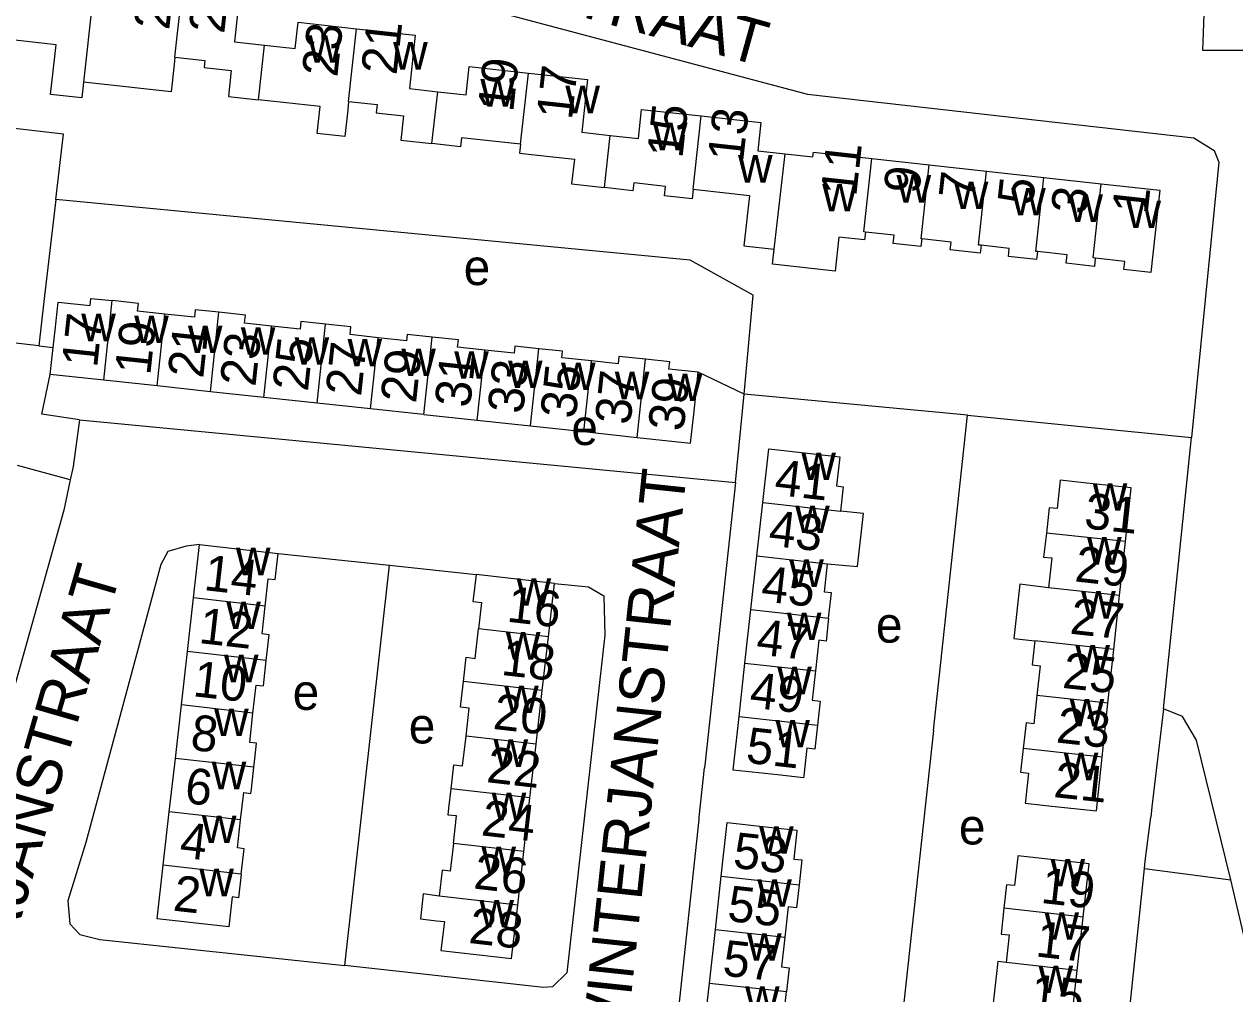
# Model space of a CAD drawing. Extents: x 161936 to 163647, y 386450 to 388633.
# Drawn here: x 162355.2 to 162490.7, y 387685.1 to 387793.6 of the extents above; entities that cross this region are included whole.
import ezdxf

# ---------------------------------------------------------------- set-up
doc = ezdxf.new("R2010")
doc.units = 0
for name, color, linetype in [('BLT_Basislijn', 7, 'Continuous'), ('BLT_Bebouwing', 7, 'Continuous'), ('BLT_Centroide', 7, 'Continuous'), ('BLT_Huisnummer', 7, 'Continuous'), ('BLT_Huisnummer_ tussenligend', 7, 'Continuous'), ('BLT_Onderverdeling_panden', 7, 'Continuous'), ('BLT_Straatnaam', 7, 'Continuous'), ('BLT_Vlakafsluiter', 7, 'Continuous')]:
    doc.layers.add(name, color=color, linetype=linetype)

msp = doc.modelspace()

# ---------------------------------------------------------------- linework, layer by layer
at = {"layer": 'BLT_Basislijn'}
for p, q in [((162356.86, 387757.65), (162358.48, 387757.44)), ((162434.82, 387742.35), (162435.82, 387752.22)), ((162460.8, 387749.87), (162435.82, 387752.22)), ((162457, 387714.58), (162460.8, 387749.87)), ((162460.8, 387749.87), (162485.87, 387747.39)), ((162361.43, 387749.36), (162434.82, 387742.35)), ((162482.75, 387717.02), (162485.87, 387747.39)), ((162360.39, 387742.63), (162354.47, 387744.25)), ((162383.65, 387734.4), (162396.12, 387733.09)), ((162391.1, 387688.31), (162396.12, 387733.09)), ((162396.12, 387733.09), (162405.8, 387732.07)), ((162457, 387714.58), (162448.91, 387640.49)), ((162427.81, 387677.24), (162430.77, 387704.64)), ((162474.31, 387639.43), (162480.61, 387699.15)), ((162480.61, 387699.15), (162490.26, 387697.9))]:
    msp.add_line(p, q, dxfattribs=at)
for points in [[(162502.48, 387814.29), (162501.34, 387810.13), (162499.33, 387800.3), (162497.01, 387793.33), (162495.42, 387791.61), (162493.28, 387790.67), (162487.12, 387790.69), (162487.41, 387797.79)], [(162303.81, 387812.76), (162305.9, 387812.89), (162310.22, 387812.55), (162362.08, 387807.27), (162442.89, 387785.78), (162486.12, 387780.93), (162488.41, 387779.48), (162488.92, 387778.18), (162485.87, 387747.39)], [(162436.82, 387763.29), (162429.77, 387767.21), (162358.77, 387774.02)], [(162435.82, 387752.22), (162436.82, 387763.29)], [(162361.43, 387749.36), (162357.2, 387750.01), (162358.16, 387754.43)], [(162361.43, 387749.36), (162360.71, 387744.14), (162360.39, 387742.63)], [(162360.39, 387742.63), (162359.67, 387739.24), (162347.85, 387697.16), (162347.68, 387696.55)], [(162434.82, 387742.35), (162431.44, 387711.06), (162431.38, 387710.43)], [(162374.87, 387735.4), (162373.38, 387735.23), (162371.32, 387734.62), (162370.52, 387733.19), (162362.13, 387702.07), (162360.11, 387695.53), (162360.35, 387692.95), (162361.45, 387691.77), (162363.71, 387691.23), (162391.1, 387688.31)], [(162414.59, 387731.06), (162418.38, 387730.66), (162420.12, 387729.68), (162420.23, 387725.26), (162415.98, 387687.47), (162414.37, 387685.93), (162413.34, 387685.85), (162391.1, 387688.31)], [(162482.75, 387717.02), (162481.44, 387706.07), (162481.3, 387704.89)], [(162490.26, 387697.9), (162486.44, 387713.53), (162484.85, 387716.16), (162482.75, 387717.02)], [(162430.77, 387704.64), (162430.79, 387704.9), (162431.38, 387710.43)], [(162480.61, 387699.15), (162480.69, 387699.98), (162481.3, 387704.89)], [(162481.44, 387634.62), (162492.55, 387679.45), (162492.68, 387685.02), (162492.39, 387688.84), (162490.26, 387697.9)]]:
    msp.add_lwpolyline(points, dxfattribs=at)
at = {"layer": 'BLT_Bebouwing'}
for p, q in [((162450.11, 387778.59), (162456.52, 387777.88)), ((162456.52, 387777.88), (162462.93, 387777.18)), ((162462.93, 387777.18), (162469.35, 387776.47)), ((162469.35, 387776.47), (162475.76, 387775.77)), ((162358.16, 387754.43), (162358.48, 387757.44)), ((162364.13, 387753.79), (162358.16, 387754.43)), ((162370.1, 387753.15), (162364.13, 387753.79)), ((162376.08, 387752.51), (162370.1, 387753.15)), ((162382.05, 387751.87), (162376.08, 387752.51)), ((162388.02, 387751.24), (162382.05, 387751.87)), ((162393.99, 387750.6), (162388.02, 387751.24)), ((162399.96, 387749.96), (162405.93, 387749.32)), ((162405.93, 387749.32), (162411.9, 387748.68)), ((162411.9, 387748.68), (162417.87, 387748.04)), ((162417.87, 387748.04), (162423.84, 387747.4)), ((162437.24, 387734.13), (162437.91, 387740.12)), ((162374.19, 387729.43), (162374.87, 387735.4)), ((162374.87, 387735.4), (162383.65, 387734.4)), ((162477.83, 387729.71), (162478.48, 387735.73)), ((162436.57, 387728.14), (162437.24, 387734.13)), ((162414.59, 387731.06), (162405.8, 387732.07)), ((162413.9, 387725.07), (162414.59, 387731.06)), ((162373.51, 387723.45), (162374.19, 387729.43)), ((162477.18, 387723.68), (162477.83, 387729.71)), ((162435.9, 387722.15), (162436.57, 387728.14)), ((162413.21, 387719.07), (162413.9, 387725.07)), ((162372.83, 387717.46), (162373.51, 387723.45)), ((162476.52, 387717.66), (162477.18, 387723.68)), ((162435.23, 387716.16), (162435.9, 387722.15)), ((162412.53, 387713.07), (162413.21, 387719.07)), ((162372.15, 387711.48), (162372.83, 387717.46)), ((162475.88, 387711.63), (162476.52, 387717.66)), ((162434.56, 387710.17), (162435.23, 387716.16)), ((162411.84, 387707.07), (162412.53, 387713.07)), ((162371.47, 387705.5), (162372.15, 387711.48)), ((162475.23, 387705.6), (162475.88, 387711.63)), ((162411.15, 387701.07), (162411.84, 387707.07)), ((162370.79, 387699.52), (162371.47, 387705.5)), ((162433.25, 387698.31), (162433.92, 387704.3)), ((162410.46, 387695.07), (162411.15, 387701.07)), ((162473.74, 387693.72), (162474.41, 387699.68)), ((162432.59, 387692.32), (162433.25, 387698.31)), ((162473.06, 387687.75), (162473.74, 387693.72)), ((162431.93, 387686.33), (162432.59, 387692.32)), ((162472.39, 387681.78), (162473.06, 387687.75)), ((162431.26, 387680.35), (162431.93, 387686.33))]:
    msp.add_line(p, q, dxfattribs=at)
for points in [[(162373.02, 387798.35), (162379.42, 387797.64), (162378.76, 387791.64), (162382.14, 387791.27)], [(162361.89, 387787.14), (162361.69, 387785.37), (162358.19, 387785.76), (162358.81, 387791.33), (162352.53, 387792.02), (162352.75, 387794.03)], [(162382.14, 387791.27), (162385.56, 387790.89), (162385.88, 387793.84), (162392.44, 387793.12)], [(162392.44, 387793.12), (162399, 387792.4), (162398.35, 387786.42), (162401.51, 387786.07)], [(162372.1, 387789.95), (162372.02, 387789.13), (162371.68, 387786.05), (162361.89, 387787.14)], [(162372.1, 387789.95), (162375.46, 387789.58), (162375.37, 387788.77), (162378.41, 387788.43), (162378.1, 387785.53), (162381.46, 387785.16)], [(162401.51, 387786.07), (162404.68, 387785.72), (162405.02, 387788.89), (162411.66, 387788.16)], [(162411.66, 387788.16), (162418.29, 387787.43), (162417.64, 387781.53), (162420.81, 387781.18)], [(162391.54, 387784.98), (162391.44, 387784.06), (162391.11, 387781.07), (162388.03, 387781.41), (162388.36, 387784.4), (162381.46, 387785.16)], [(162391.54, 387784.98), (162394.74, 387784.63), (162394.64, 387783.71), (162397.68, 387783.38), (162397.39, 387780.64), (162400.87, 387780.26)], [(162358.77, 387774.02), (162359.62, 387781.31), (162336, 387784.06)], [(162420.81, 387781.18), (162423.98, 387780.83), (162424.33, 387784.09), (162431.01, 387783.36)], [(162431.01, 387783.36), (162437.68, 387782.62), (162437.33, 387779.46), (162440.41, 387779.12)], [(162410.78, 387780.19), (162404.17, 387780.92), (162404.06, 387779.91), (162400.87, 387780.26)], [(162410.78, 387780.19), (162410.67, 387779.18), (162413.74, 387778.85), (162416.81, 387778.51), (162416.5, 387775.75), (162420.17, 387775.34)], [(162440.41, 387779.12), (162443.49, 387778.79), (162443.55, 387779.31), (162450.11, 387778.59)], [(162356.86, 387757.65), (162351.03, 387758.32), (162353.1, 387776.06), (162341.35, 387777.43), (162338.25, 387750.82)], [(162430.1, 387775.15), (162429.99, 387774.1), (162426.88, 387774.44), (162427, 387775.48), (162423.46, 387775.87), (162423.36, 387774.99), (162420.17, 387775.34)], [(162475.76, 387775.77), (162482.33, 387775.04), (162481.31, 387765.86), (162478.31, 387766.19), (162478.41, 387767.08), (162475.1, 387767.45)], [(162430.1, 387775.15), (162436.4, 387774.45), (162435.78, 387768.83), (162439.18, 387768.45)], [(162358.77, 387774.02), (162357.44, 387762.61), (162356.86, 387757.65)], [(162449.37, 387770.37), (162449.28, 387769.49), (162446.4, 387769.81), (162445.98, 387765.99), (162438.99, 387766.76)], [(162455.68, 387769.6), (162455.59, 387768.76), (162452.48, 387769.1), (162452.58, 387770.02), (162449.37, 387770.37)], [(162462.32, 387768.89), (162462.22, 387768), (162458.87, 387768.37), (162458.96, 387769.23), (162455.68, 387769.6)], [(162468.63, 387768.19), (162468.53, 387767.29), (162465.38, 387767.64), (162465.48, 387768.54), (162462.32, 387768.89)], [(162438.99, 387766.76), (162439.18, 387768.45)], [(162475.1, 387767.45), (162475, 387766.52), (162471.86, 387766.87), (162471.96, 387767.82), (162468.63, 387768.19)], [(162358.48, 387757.44), (162358.69, 387759.4), (162359.03, 387762.52), (162362.62, 387762.14), (162362.71, 387762.95), (162365.09, 387762.7)], [(162370.96, 387761.18), (162367.91, 387761.51), (162368.01, 387762.38), (162365.09, 387762.7)], [(162377.03, 387761.4), (162374.37, 387761.68), (162374.28, 387760.83), (162370.96, 387761.18)], [(162382.9, 387759.84), (162379.9, 387760.16), (162380, 387761.08), (162377.03, 387761.4)], [(162388.96, 387760.08), (162386.21, 387760.37), (162386.11, 387759.5), (162382.9, 387759.84)], [(162394.84, 387758.55), (162391.7, 387758.89), (162391.79, 387759.77), (162388.96, 387760.08)], [(162400.89, 387758.62), (162398.09, 387758.92), (162398.01, 387758.21), (162394.84, 387758.55)], [(162406.77, 387757.17), (162403.74, 387757.49), (162403.83, 387758.31), (162400.89, 387758.62)], [(162412.82, 387757.32), (162410.16, 387757.6), (162410.08, 387756.81), (162406.77, 387757.17)], [(162418.72, 387755.95), (162415.39, 387756.31), (162415.47, 387757.04), (162412.82, 387757.32)], [(162424.78, 387756.14), (162421.8, 387756.46), (162421.71, 387755.63), (162418.72, 387755.95)], [(162430.66, 387754.69), (162427.39, 387755.04), (162427.48, 387755.85), (162424.78, 387756.14)], [(162423.84, 387747.4), (162429.81, 387746.76), (162430.16, 387750), (162430.35, 387751.74), (162430.66, 387754.69)], [(162399.96, 387749.96), (162399.56, 387750), (162393.99, 387750.6)], [(162437.91, 387740.12), (162438.58, 387746.1)], [(162438.58, 387746.1), (162443.55, 387745.55), (162446.52, 387745.22), (162446.15, 387741.97), (162446.9, 387741.88), (162446.6, 387739.14)], [(162479.12, 387741.76), (162474.15, 387742.29), (162471.17, 387742.62), (162470.83, 387739.42), (162469.95, 387739.52), (162469.63, 387736.69)], [(162478.48, 387735.73), (162479.12, 387741.76)], [(162445.15, 387733.24), (162448.5, 387732.94), (162449.18, 387738.89), (162446.6, 387739.14)], [(162469.63, 387736.69), (162469.32, 387734.01), (162470.23, 387733.9), (162469.87, 387730.57)], [(162382.2, 387728.52), (162382.55, 387731.57), (162383.32, 387731.48), (162383.65, 387734.4)], [(162445.26, 387727.17), (162445.58, 387729.99), (162444.8, 387730.08), (162445.15, 387733.24)], [(162405.8, 387732.07), (162405.48, 387729.31), (162405.45, 387729.04), (162406.41, 387728.93), (162406.07, 387725.97)], [(162469.87, 387730.57), (162466.66, 387730.96), (162466, 387724.88), (162468.33, 387724.64)], [(162382.33, 387722.44), (162382.66, 387725.31), (162381.85, 387725.41), (162382.2, 387728.52)], [(162445.26, 387727.17), (162444.98, 387724.6), (162444.18, 387724.69), (162443.8, 387721.27)], [(162404.39, 387720.08), (162404.7, 387722.79), (162405.7, 387722.67), (162406.07, 387725.97)], [(162468.33, 387724.64), (162468.02, 387721.95), (162468.93, 387721.85), (162468.57, 387718.51)], [(162380.84, 387716.55), (162381.2, 387719.67), (162382.01, 387719.58), (162382.33, 387722.44)], [(162443.8, 387721.27), (162443.43, 387717.99), (162444.33, 387717.89), (162444.03, 387715.18)], [(162404.68, 387713.97), (162405.04, 387717.09), (162404.06, 387717.21), (162404.1, 387717.56), (162404.39, 387720.08)], [(162468.57, 387718.51), (162468.23, 387715.36), (162467.35, 387715.46), (162467.03, 387712.58)], [(162380.95, 387710.48), (162381.05, 387711.41), (162381.25, 387713.17), (162380.47, 387713.26), (162380.84, 387716.55)], [(162444.03, 387715.18), (162443.73, 387712.51), (162442.83, 387712.61), (162442.49, 387709.51)], [(162403.01, 387708.08), (162403.31, 387710.76), (162404.3, 387710.64), (162404.68, 387713.97)], [(162467.03, 387712.58), (162466.73, 387709.94), (162467.64, 387709.84), (162467.3, 387706.74)], [(162379.45, 387704.6), (162379.8, 387707.66), (162380.61, 387707.56), (162380.67, 387708.04), (162380.95, 387710.48)], [(162442.49, 387709.51), (162442.46, 387709.29), (162439.52, 387709.62), (162434.56, 387710.17)], [(162403.27, 387701.97), (162403.62, 387705.04), (162402.67, 387705.14), (162402.76, 387705.9), (162403.01, 387708.08)], [(162467.3, 387706.74), (162467.27, 387706.46), (162470.25, 387706.14), (162475.23, 387705.6)], [(162379.53, 387698.53), (162379.85, 387701.37), (162379.09, 387701.46), (162379.45, 387704.6)], [(162433.92, 387704.3), (162438.89, 387703.74), (162441.72, 387703.43), (162441.71, 387703.33)], [(162441.71, 387703.33), (162441.37, 387700.22), (162442.26, 387700.12), (162441.95, 387697.34)], [(162403.27, 387701.97), (162402.91, 387698.87), (162402.01, 387698.98), (162401.67, 387696.08)], [(162466.43, 387700.45), (162466.07, 387697.24), (162465.18, 387697.34), (162464.88, 387694.72)], [(162474.41, 387699.68), (162469.44, 387700.24), (162466.45, 387700.58), (162466.43, 387700.45)], [(162379.53, 387698.53), (162379.23, 387695.89), (162378.52, 387695.97), (162378.14, 387692.63), (162370.12, 387693.54), (162370.79, 387699.52)], [(162441.95, 387697.34), (162441.67, 387694.74), (162440.73, 387694.85), (162440.35, 387691.46)], [(162401.67, 387696.08), (162399.89, 387696.32), (162399.57, 387693.52), (162401.36, 387693.31), (162402.26, 387693.21), (162401.88, 387689.97), (162409.77, 387689.07), (162410.46, 387695.07)], [(162464.88, 387694.72), (162464.56, 387691.82), (162465.45, 387691.72), (162465.11, 387688.65)], [(162440.35, 387691.46), (162439.98, 387688.14), (162440.83, 387688.05), (162440.54, 387685.38)], [(162465.11, 387688.65), (162464.21, 387688.75), (162463.84, 387685.45), (162463.54, 387682.78)], [(162439.08, 387679.48), (162439.45, 387682.83), (162440.24, 387682.74), (162440.54, 387685.38)]]:
    msp.add_lwpolyline(points, dxfattribs=at)
at = {"layer": 'BLT_Onderverdeling_panden'}
for p, q in [((162372.1, 387789.95), (162373.02, 387798.35)), ((162362.89, 387796.24), (162361.89, 387787.14)), ((162391.54, 387784.98), (162392.44, 387793.12)), ((162381.46, 387785.16), (162382.14, 387791.27)), ((162410.78, 387780.19), (162411.66, 387788.16)), ((162400.87, 387780.26), (162401.51, 387786.07)), ((162430.1, 387775.15), (162431.01, 387783.36)), ((162420.17, 387775.34), (162420.81, 387781.18)), ((162439.18, 387768.45), (162440.41, 387779.12)), ((162364.13, 387753.79), (162365.09, 387762.7)), ((162370.1, 387753.15), (162370.96, 387761.18)), ((162376.08, 387752.51), (162377.03, 387761.4)), ((162382.05, 387751.87), (162382.9, 387759.84)), ((162388.02, 387751.24), (162388.96, 387760.08)), ((162393.99, 387750.6), (162394.84, 387758.55)), ((162399.96, 387749.96), (162400.89, 387758.62)), ((162405.93, 387749.32), (162406.77, 387757.17)), ((162411.9, 387748.68), (162412.82, 387757.32)), ((162417.87, 387748.04), (162418.72, 387755.95)), ((162423.84, 387747.4), (162424.78, 387756.14)), ((162437.91, 387740.12), (162446.6, 387739.14)), ((162478.48, 387735.73), (162469.63, 387736.69)), ((162437.24, 387734.13), (162445.15, 387733.24)), ((162382.2, 387728.52), (162374.19, 387729.43)), ((162477.83, 387729.71), (162469.87, 387730.57)), ((162436.57, 387728.14), (162445.26, 387727.17)), ((162413.9, 387725.07), (162406.07, 387725.97)), ((162477.18, 387723.68), (162468.33, 387724.64)), ((162382.33, 387722.44), (162373.51, 387723.45)), ((162435.9, 387722.15), (162443.8, 387721.27)), ((162413.21, 387719.07), (162404.39, 387720.08)), ((162380.84, 387716.55), (162372.83, 387717.46)), ((162476.52, 387717.66), (162468.57, 387718.51)), ((162435.23, 387716.16), (162444.03, 387715.18)), ((162412.53, 387713.07), (162404.68, 387713.97)), ((162475.88, 387711.63), (162467.03, 387712.58)), ((162380.95, 387710.48), (162372.15, 387711.48)), ((162411.84, 387707.07), (162403.01, 387708.08)), ((162379.45, 387704.6), (162371.47, 387705.5)), ((162411.15, 387701.07), (162403.27, 387701.97)), ((162379.53, 387698.53), (162370.79, 387699.52)), ((162433.25, 387698.31), (162441.95, 387697.34)), ((162410.46, 387695.07), (162401.67, 387696.08)), ((162473.74, 387693.72), (162464.88, 387694.72)), ((162432.59, 387692.32), (162440.35, 387691.46)), ((162473.06, 387687.75), (162465.11, 387688.65)), ((162431.93, 387686.33), (162440.54, 387685.38))]:
    msp.add_line(p, q, dxfattribs=at)
for points in [[(162449.37, 387770.37), (162449.21, 387770.39), (162450.11, 387778.59)], [(162455.68, 387769.6), (162455.61, 387769.6), (162456.52, 387777.88)], [(162462.32, 387768.89), (162462.03, 387768.92), (162462.93, 387777.18)], [(162468.63, 387768.19), (162468.44, 387768.21), (162469.35, 387776.47)], [(162475.1, 387767.45), (162474.85, 387767.48), (162475.76, 387775.77)]]:
    msp.add_lwpolyline(points, dxfattribs=at)
at = {"layer": 'BLT_Vlakafsluiter'}
msp.add_line((162435.82, 387752.22), (162430.66, 387754.69), dxfattribs=at)

# ---------------------------------------------------------------- texts
at = {"layer": 'BLT_Centroide'}
for s, p in [('w', (162386.97, 387789.31)), ('w', (162396.53, 387788.55)), ('w', (162406.29, 387784.41)), ('w', (162415.8, 387783.67)), ('w', (162425.6, 387779.53)), ('w', (162435.12, 387775.91)), ('w', (162444.55, 387772.67)), ('w', (162452.86, 387773.67)), ('w', (162459.27, 387772.95)), ('w', (162465.69, 387772.23)), ('w', (162472.09, 387771.5)), ('w', (162478.59, 387770.81)), ('e', (162404.42, 387764.44)), ('w', (162361.62, 387758.16)), ('w', (162367.55, 387757.94)), ('w', (162373.56, 387756.84)), ('w', (162379.48, 387756.64)), ('w', (162385.5, 387755.53)), ('w', (162391.42, 387755.34)), ('w', (162397.44, 387754.25)), ('w', (162403.36, 387753.97)), ('w', (162409.38, 387752.91)), ('w', (162415.31, 387752.69)), ('w', (162421.33, 387751.67)), ('w', (162427.25, 387751.45)), ('e', (162416.47, 387746.54)), ('w', (162442.21, 387742.62)), ('w', (162474.82, 387739.19)), ('w', (162441.52, 387736.69)), ('w', (162474.18, 387733.16)), ('w', (162378.93, 387731.97)), ('w', (162440.85, 387730.66)), ('w', (162410.34, 387728.56)), ('w', (162473.52, 387727.12)), ('w', (162377.85, 387725.94)), ('w', (162440.59, 387724.72)), ('e', (162450.55, 387724.43)), ('w', (162409.14, 387722.53)), ('w', (162472.87, 387721.09)), ('w', (162377.59, 387720)), ('w', (162439.51, 387718.66)), ('e', (162385.28, 387716.91)), ('w', (162408.95, 387716.56)), ('w', (162472.23, 387715.06)), ('w', (162376.49, 387713.97)), ('e', (162398.27, 387713.15)), ('w', (162439.3, 387712.72)), ('w', (162407.76, 387710.53)), ('w', (162471.57, 387709.03)), ('w', (162376.22, 387708.03)), ('w', (162407.55, 387704.56)), ('w', (162375.12, 387702)), ('w', (162437.48, 387700.81)), ('e', (162459.84, 387701.85)), ('w', (162406.41, 387698.53)), ('w', (162470.09, 387697.16)), ('w', (162374.83, 387696.06)), ('w', (162437.28, 387694.88)), ('w', (162406.18, 387692.56)), ('w', (162469.42, 387691.19)), ('w', (162436.13, 387688.84)), ('w', (162468.75, 387685.22)), ('w', (162435.91, 387682.91))]:
    msp.add_text(s, height=4, dxfattribs=at).set_placement(p)
at = {"layer": 'BLT_Huisnummer'}
for s, rotation, p in [('25', 83.7268, (162377.61, 387792.49)), ('21', 83.7261, (162396.9, 387787.86)), ('17', 83.7142, (162416.53, 387782.85)), ('13', 83.7242, (162435.68, 387778.12)), ('9', 83.7281, (162455.38, 387774.57)), ('5', 83.7281, (162468.12, 387773.3)), ('1', 83.7139, (162480.95, 387772.29)), ('17', 83.8948, (162363.39, 387755.12)), ('21', 83.89, (162375.26, 387753.93)), ('25', 83.8916, (162386.98, 387752.46)), ('29', 83.8966, (162399.08, 387751.14)), ('33', 83.8967, (162411.05, 387749.95)), ('39', 83.9137, (162429.02, 387747.99)), ('41', 353.6121, (162439.1, 387740.99)), ('31', 353.8433, (162473.76, 387737.24)), ('14', 353.5193, (162375.24, 387730.32)), ('45', 353.6157, (162437.6, 387729.08)), ('16', 353.4612, (162409.15, 387726.79)), ('25', 353.8433, (162471.33, 387719.38)), ('10', 353.5248, (162374.02, 387718.45)), ('20', 353.4634, (162407.61, 387714.79)), ('51', 353.6155, (162435.91, 387711.01)), ('6', 353.5187, (162373.09, 387706.5)), ('21', 353.8458, (162470.35, 387707.16)), ('24', 353.4605, (162406.29, 387702.88)), ('53', 353.6776, (162434.46, 387699.25)), ('2', 353.5156, (162371.8, 387694.46)), ('19', 353.5722, (162468.91, 387695.32)), ('28', 353.4646, (162404.89, 387690.84)), ('57', 353.6766, (162433.29, 387687.2))]:
    msp.add_text(s, height=4, rotation=rotation, dxfattribs=at).set_placement(p)
at = {"layer": 'BLT_Huisnummer_ tussenligend'}
for s, rotation, p in [('27', 83.7268, (162371.45, 387792.9)), ('23', 83.7261, (162390.27, 387787.63)), ('19', 83.7142, (162409.95, 387783.71)), ('15', 83.7242, (162428.89, 387778.54)), ('11', 83.7274, (162448.34, 387774.27)), ('7', 83.7281, (162461.54, 387773.93)), ('3', 83.7139, (162474.1, 387772.27)), ('19', 83.8948, (162369.34, 387754.28)), ('23', 83.89, (162381.11, 387753)), ('27', 83.8916, (162392.93, 387751.91)), ('31', 83.8966, (162405.13, 387750.64)), ('35', 83.8967, (162416.95, 387749.41)), ('37', 83.8967, (162423.06, 387748.71)), ('43', 353.6121, (162438.44, 387735.3)), ('29', 353.8433, (162472.71, 387731.29)), ('27', 353.8433, (162472.17, 387725.44)), ('12', 353.5248, (162374.67, 387724.4)), ('47', 353.6157, (162437.06, 387723.13)), ('18', 353.4612, (162408.52, 387720.83)), ('49', 353.6157, (162436.32, 387717.18)), ('23', 353.8458, (162470.64, 387713.27)), ('8', 353.5187, (162373.74, 387712.45)), ('22', 353.4634, (162406.88, 387708.83)), ('4', 353.5156, (162372.53, 387700.41)), ('26', 353.4605, (162405.44, 387696.93)), ('55', 353.6776, (162433.83, 387693.3)), ('17', 353.5714, (162468.33, 387689.33)), ('15', 353.5714, (162467.7, 387683.38))]:
    msp.add_text(s, height=4, rotation=rotation, dxfattribs=at).set_placement(p)
at = {"layer": 'BLT_Straatnaam'}
for s, rotation, p in [('STERAPPELSTRAAT', 344.4852, (162374.22, 387806.5)), ('WINTERJANSTRAAT', 83.934, (162422.49, 387678.52)), ('WINTERJANSTRAAT', 73.8894, (162347.91, 387669.38))]:
    msp.add_text(s, height=5, rotation=rotation, dxfattribs=at).set_placement(p)

doc.saveas('drawing.dxf')
